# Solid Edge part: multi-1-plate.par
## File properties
Author: Deepak Maini
Template: Normal.par
Last saved by: CADCIM
Revision: 6
Application: Solid Edge
Accuracy: 0.99
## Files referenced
..\multi-cutout.asm
ED:\sld-edg-15\cd-models\c09-sld-edg-15\figure28-8&29\multi-cutout.asm
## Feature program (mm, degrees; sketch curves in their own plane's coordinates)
sketch for "unnamed Protrusion 1" plane through (0, 0, 0) normal (0, 0, 1) x-axis (1, 0, 0)
  arc centre (-57, 0) radius 14.3058 from (-63.4487, -12.7699) to (-63.4487, 12.7699) cw
  line (-63.4487, 12.7699) -> (-18.031, 35.7055)
  arc centre (0, 0) radius 40 from (-18.031, 35.7055) to (18.1555, 35.6424) cw
  line (18.1555, 35.6424) -> (63.4127, 12.5893)
  arc centre (57, 0) radius 14.1284 from (63.4127, 12.5893) to (63.4127, -12.5893) cw
  line (63.4127, -12.5893) -> (18.1555, -35.6424)
  arc centre (0, 0) radius 40 from (18.1555, -35.6424) to (-18.031, -35.7055) cw
  line (-63.4487, -12.7699) -> (-18.031, -35.7055)
extrude "unnamed Protrusion 1" add finite 6.5 symmetric
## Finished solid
Body 1: solid body, 10 faces, 24 edges, 16 vertices.
  Faces by surface: plane 6, cylinder 4
  Edges by curve: line 16, circle 8
Bounding box of the edges (mm): 142.434 x 80.000 x 6.500, from (-71.3058, -40, -3.25) to (71.1284, 40, 3.25).
Cylindrical faces by radius (mm): R14.1284 x1, R14.3058 x1, R40 x2
Planar faces by outward normal: +z 1, -z 1, oblique 4
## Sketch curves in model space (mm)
arc centre (0, 0, 0) radius 40 from (-18.031, 35.7055, 0) through (0.0698, 39.9999, 0) to (18.1555, 35.6424, 0)
line (18.1555, 35.6424, 0) -> (63.4127, 12.5893, 0)
arc centre (57, 0, 0) radius 14.1284 from (63.4127, 12.5893, 0) through (71.1222, -0.4198, 0) to (63.4127, -12.5893, 0)
line (63.4127, -12.5893, 0) -> (18.1555, -35.6424, 0)
arc centre (0, 0, 0) radius 40 from (18.1555, -35.6424, 0) through (0.0698, -39.9999, 0) to (-18.031, -35.7055, 0)
line (-63.4487, -12.7699, 0) -> (-18.031, -35.7055, 0)
arc centre (-57, 0, 0) radius 14.3058 from (-63.4487, -12.7699, 0) through (-71.2995, 0.4265, 0) to (-63.4487, 12.7699, 0)
line (-63.4487, 12.7699, 0) -> (-18.031, 35.7055, 0)
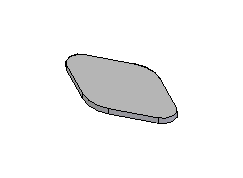
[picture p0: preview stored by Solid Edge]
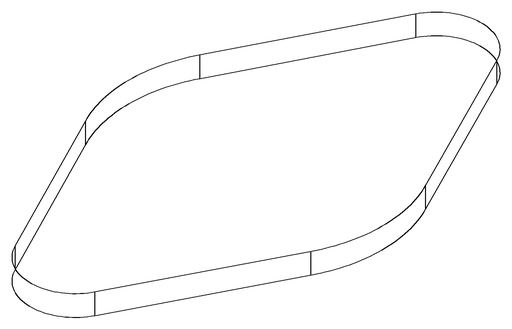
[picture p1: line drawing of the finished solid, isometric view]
